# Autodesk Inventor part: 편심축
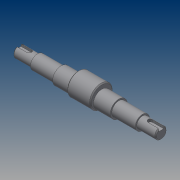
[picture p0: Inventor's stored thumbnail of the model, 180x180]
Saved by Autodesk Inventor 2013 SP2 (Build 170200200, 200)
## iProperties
Created: 2014-12
Part Number: 편심축
Material: Generic
Document SubType Name: Modeling
Designer: CADB201
Density: 1 g/cm^3
Author: CADB201
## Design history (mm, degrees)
sketch "스케치1"
  geometry: L1 (-75.5, 0)-(75.5, 0); L2 (-75.5, 0)-(-75.5, 6); L3 (-75.5, 6)-(-55.5, 6); L4 (-55.5, 6)-(-55.5, 7.5); L5 (-55.5, 7.5)-(-30.5, 7.5); L6 (-30.5, 7.5)-(-30.5, 9); L7 (-30.5, 9)-(30.5, 9); L8 (30.5, 9)-(30.5, 7.5); L9 (30.5, 7.5)-(55.5, 7.5); L10 (55.5, 7.5)-(55.5, 6); L11 (55.5, 6)-(75.5, 6); L12 (75.5, 6)-(75.5, 0); L13 (-12.5, 14)-(12.5, 14); L14 (12.5, 14)-(12.5, 2); L15 (12.5, 2)-(-12.5, 2); L16 (-12.5, 2)-(-12.5, 14); 3 further points
  constraints: 32 end point, 8 parallel, 6 perpendicular, 2 collinear, 2 horizontal, 2 midpoint, 1 coincident, 1 vertical alignment
  dimensions: "d0" = 151 distance of L1.start L1.end; "d2" = 12 diameter of L3 L1; "d3" = 15 diameter of L5 L1; "d4" = 18 diameter of L7 L1; "d5" = 20 distance of L2.end L3.end; "d6" = 25 distance of L4.end L5.end; "d7" = 20 distance of L10.end L11.end; "d8" = 25 distance of L8.end L9.end; "d9" = 4 diameter of L15 L1; "d10" = 12 distance between parallel lines of L13 L15; "d11" = 18 distance from line of L16 L6.end
revolve "회전1" stored, may be unused: angle "d12" = 90 deg
revolve "회전2" stored, may be unused: angle "d13" = 90 deg
node "작업 평면1"
sketch "스케치2"
  geometry: L1 (-10, 6)-(-10, -6) reference; L2 (10, 7.5)-(10, -7.5) reference; L3 (-12.726, 2.5)-(4, 2.5); L4 (4, 2.5)-(4, -2.5); L5 (4, -2.5)-(-12.726, -2.5); L6 (-12.726, -2.5)-(-12.726, 2.5); 3 further points
  constraints: 8 end point, 2 midpoint, 2 parallel, 1 horizontal, 1 horizontal alignment, 1 perpendicular
  dimensions: "d14" = 14 distance between parallel lines of L4 L1; "d15" = 5 distance of L5.end L3.start
extrude "돌출1" cut sketch "스케치2" distance "d16" = 3; taper "d17" = 0 deg
fillet "모깎기1" dims "d18" = 2.5
chamfer "모따기1" distance "d19" = 1; stored, may be unused: second distance "d20" = 2, angle "d21" = 45 deg
node "솔리드1"
mirror "대칭1"
